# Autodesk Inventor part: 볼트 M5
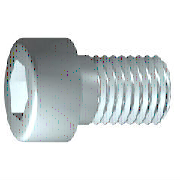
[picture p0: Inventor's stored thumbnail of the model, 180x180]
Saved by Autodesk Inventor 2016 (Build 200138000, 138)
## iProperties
IsCustomPart: 1
Created: 2012-02
Part Number: 볼트 M5
Material: 강철, 연강
Description: 6각머리 태핑 나사
Document SubType Name: Modeling
Standard: KS B 1003
Designer: mduedu
Standards Organization: KS
Language: ko-KR
Size Designation: M 5 x 16
Categories: <MemberInstance><Categories><Category DisplayName="조임쇠" InternalName="e4da775c-781d-43d5-af7c-5136215cf5a6" Mnemonic="FSTN"><Category DisplayName="볼트" InternalN
Density: 1 g/cm^3
Appearance: 강철
Author: mduedu
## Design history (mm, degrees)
sketch "스케치1"
  geometry: L1 (-1.167, 0)-(16, 0); L2 (16, 0)-(16, 2.5); L3 (16, 2.5)-(2, 2.5); L4 (2, 2.5)-(1.509, 2.5); L5 (1.509, 2.5)-(0, 2.5); L6 (0, 2.5)-(0, 4.25); L7 (0, 4.25)-(-5, 4.25); L8 (-5, 4.25)-(-5, 2.309); L9 (-5, 2.309)-(-2.5, 2.309); L10 (-2.5, 2.309)-(-1.167, 0); L11 (-9.2, 0)-(20.2, 0) reference; L12 (0, -0.85)-(0, 5.1) reference; L13 (2, 2.5)-(0, 2.5)
  constraints: 22 end point, 6 parallel, 2 collinear, 2 perpendicular, 1 horizontal, 1 point on line
  dimensions: "d1" = 14 distance from line of L3.end L2 (= GEL); "d2" = 0.49086 distance of L4.end L3.end (computed from GAL); "d3" = 5 distance between parallel lines of L8 L6 (= KOH); "d4" = 2.5 distance of L8.end L9.end (= INTI); "d5" = 60 deg angle of L10 L1; "d6" = 5 diameter of L3 L1 (= GD); "d7" = 5 diameter of L5 L1 (= BDM); "d8" = 4.6188 diameter of L9 L1 (= 1.1547 x SW); "d9" = 8.5 diameter of L7 L1 (= KOD); "d26" = 16 distance between parallel lines of L12 L2 (= NLG)
revolve "본체" sketch "스케치1" stored, may be unused: angle "d10" = 90 deg
sketch "스케치2"
  geometry: L1 (0, -5.95)-(0, 5.95) reference; L2 (-5.95, 0)-(5.95, 0) reference; L3 (2.309, 0)-(1.155, -2); L4 (1.155, -2)-(-1.155, -2); L5 (-1.155, -2)-(-2.309, 0); L6 (-2.309, 0)-(-1.155, 2); L7 (-1.155, 2)-(1.155, 2); L8 (1.155, 2)-(2.309, 0); 2 further points
  constraints: 12 end point, 1 coincident, 1 horizontal alignment, 1 point on line, 12 other
extrude "슬롯" join sketch "스케치2" stored distance "d11" = 10; taper "d12" = 0 deg
workplane "Work Plane1"
fillet "Fillet2" dims "d30" = 0.1 (= R)
body "Solid1"
fillet "모깎기1" dims "d17" = 0.5 (= RR)
feature "스레드" dims "d13" = 14 (= GEL), "d14" = 0
chamfer "모따기1" distance "d15" = 0.49076 (= -0.5 x SPD + 0.5 x GD); stored, may be unused: second distance "d16" = 0.49076 (= GUL), angle "d27" = 45 deg
other parameters: "GD" = 5 (= NND) [user parameter; used in 2 equation terms], "NLG" = 16 [user parameter; used in 1 equation term], "GEL" = 14 [user parameter; used in 2 equation terms], "KOD" = 8.5 [user parameter; used in 1 equation term], "KOH" = 5 [user parameter; used in 1 equation term], "INTI" = 2.5 [user parameter; used in 1 equation term], "GAL" = 0.49076 (= 0.61345 x PTC) [user parameter; used in 1 equation term], "GUL" = 0.49076 (= 0.61345 x PTC) [user parameter; used in 1 equation term], "BDM" = 5 (= NND) [user parameter; used in 1 equation term], "SW" = 4 [user parameter; used in 2 equation terms], "RR" = 0.5 [user parameter; used in 1 equation term], "SPD" = 4.01848 (= NND - 1.2269 x PTC) [user parameter; used in 1 equation term], "d19" = 0, "d28" = 0, "d29" = 0, "R" = 0.1 [user parameter; used in 1 equation term], "PHH" = 0.2 [user parameter], "GD1" = 4.01848 (= THREADDIA - 1.2269 x PTC) [user parameter], "THREADDIA" = 5 [user parameter; used in 1 equation term], "FAWI" = 45 deg [user parameter], "TPU" = 12.5 (computed from PTC) [user parameter], "PTC" = 0.8 [user parameter; used in 5 equation terms], "NND" = 5 [user parameter; used in 3 equation terms], "TOA" = 30 deg [user parameter], "E0" = 4.62 (= 1.155 x SW) [user parameter]
